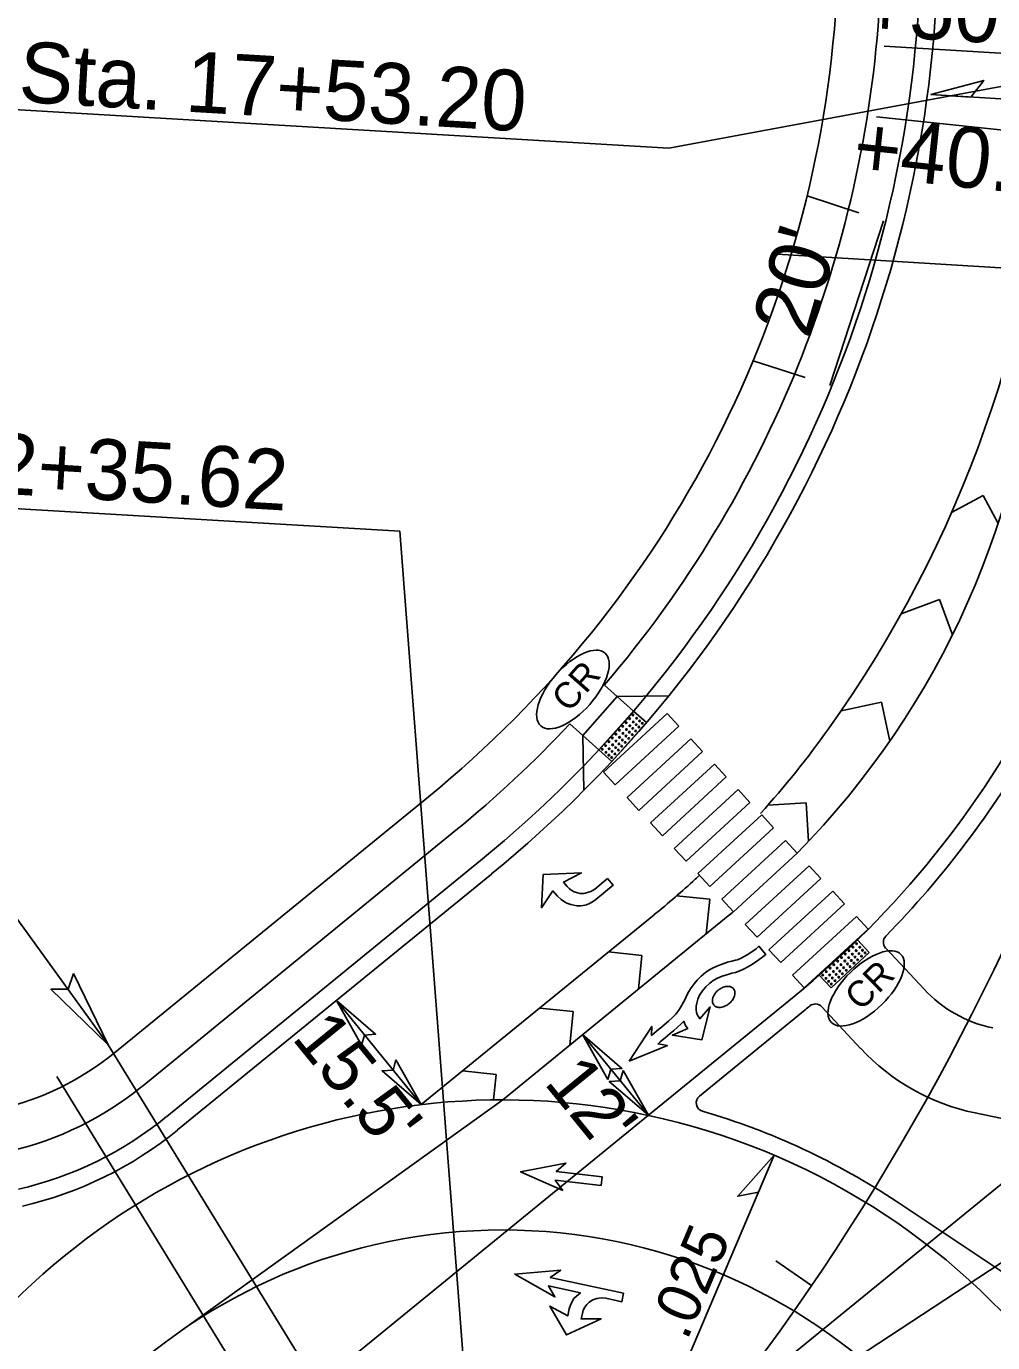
# Model space of a CAD drawing. Extents: x 2010838 to 2015151, y 441905 to 447792.
# Drawn here: x 2011912.5 to 2012023.9, y 445039.2 to 445190.9 of the extents above; entities that cross this region are included whole.
import ezdxf

# ---------------------------------------------------------------- set-up
doc = ezdxf.new("R2010")
doc.units = 0
for name, color, linetype in [('A-Wall-Abov', 7, 'Continuous'), ('A-Wall-Blow', 7, 'Continuous'), ('A-Wall-Comp', 7, 'Continuous'), ('B-Sheet Number', 7, 'Continuous'), ('C-Alignment Geometry', 7, 'Continuous'), ('C-Building', 7, 'Continuous'), ('C-CURB STOPS', 7, 'Continuous'), ('C-Grave Plots', 7, 'Continuous'), ('C-SHBD-TEXT', 7, 'Continuous'), ('C-Surface', 7, 'Continuous'), ('CLRD', 7, 'Continuous'), ('Default_10ft_LIDAR_Contou', 7, 'Continuous'), ('HATCH', 7, 'Continuous'), ('s-Existing Major', 7, 'Continuous'), ('S-Existing Minor', 7, 'Continuous'), ('S-overhead electric', 7, 'Continuous'), ('TEXT-LG', 7, 'Continuous'), ('TEXT-MED', 7, 'Continuous'), ('X2', 7, 'Continuous'), ('X3', 7, 'Continuous'), ('X4', 7, 'Continuous')]:
    doc.layers.add(name, color=color, linetype=linetype)

msp = doc.modelspace()

# ---------------------------------------------------------------- linework, layer by layer
at = {"layer": 'A-Wall-Abov'}
for points in [[(2011979.54, 445092.68), (2011980.18, 445091.91), (2011978.18, 445090.26), (2011977.8, 445089.98), (2011977.48, 445089.8), (2011977.1, 445089.64), (2011976.73, 445089.57), (2011976.43, 445089.54), (2011975.99, 445089.55), (2011975.66, 445089.6), (2011975.29, 445089.68), (2011974.86, 445089.84), (2011974.56, 445090), (2011974.19, 445090.25), (2011973.76, 445090.64), (2011973.25, 445091.26), (2011971.94, 445089.32), (2011972.13, 445093.15), (2011976.52, 445093.32), (2011974.47, 445092.27), (2011974.89, 445091.76), (2011975.15, 445091.48), (2011975.44, 445091.28), (2011975.71, 445091.15), (2011976.09, 445091.02), (2011976.38, 445090.95), (2011976.81, 445090.96), (2011977.22, 445091.05), (2011977.6, 445091.18), (2011978.06, 445091.46)], [(2011979.54, 445092.68), (2011980.18, 445091.91), (2011978.18, 445090.26), (2011977.8, 445089.98), (2011977.48, 445089.8), (2011977.1, 445089.64), (2011976.73, 445089.57), (2011976.43, 445089.54), (2011975.99, 445089.55), (2011975.66, 445089.6), (2011975.29, 445089.68), (2011974.86, 445089.84), (2011974.56, 445090), (2011974.19, 445090.25), (2011973.76, 445090.64), (2011973.25, 445091.26), (2011971.94, 445089.32), (2011972.13, 445093.15), (2011976.52, 445093.32), (2011974.47, 445092.27), (2011974.89, 445091.76), (2011975.15, 445091.48), (2011975.44, 445091.28), (2011975.71, 445091.15), (2011976.09, 445091.02), (2011976.38, 445090.95), (2011976.81, 445090.96), (2011977.22, 445091.05), (2011977.6, 445091.18), (2011978.06, 445091.46)], [(2011982.02, 445071.61), (2011984.63, 445075.63), (2011984.61, 445074.6), (2011985.2, 445075.09), (2011985.79, 445075.58), (2011986.57, 445076.25), (2011987.03, 445076.66), (2011987.41, 445077.06), (2011987.75, 445077.49), (2011987.97, 445077.82), (2011988.3, 445078.41), (2011988.38, 445078.53), (2011988.85, 445079.53), (2011989.18, 445080.07), (2011989.52, 445080.55), (2011989.86, 445080.95), (2011990.32, 445081.42), (2011990.87, 445081.87), (2011991.3, 445082.15), (2011991.58, 445082.31), (2011992.16, 445082.58), (2011992.76, 445082.82), (2011993.38, 445083.03), (2011993.86, 445083.16), (2011994.28, 445083.26), (2011994.54, 445083.32), (2011994.96, 445083.51), (2011995.63, 445083.87), (2011996.19, 445084.23), (2011996.66, 445084.59), (2011997, 445084.88), (2011997.78, 445083.94), (2011997.29, 445083.55), (2011996.76, 445083.16), (2011996.24, 445082.79), (2011995.81, 445082.52), (2011995.23, 445082.22), (2011994.79, 445082.03), (2011994.3, 445081.85), (2011993.86, 445081.75), (2011993.4, 445081.63), (2011992.74, 445081.41), (2011992.21, 445081.18), (2011991.73, 445080.93), (2011991.32, 445080.62), (2011990.86, 445080.2), (2011990.48, 445079.74), (2011990.16, 445079.24), (2011989.96, 445078.76), (2011989.82, 445078.31), (2011989.76, 445077.95), (2011989.76, 445077.53), (2011989.81, 445077.25), (2011989.89, 445077.02), (2011990.05, 445076.7), (2011990.17, 445076.52), (2011991.39, 445077.87), (2011990.43, 445074.1), (2011987.03, 445074.61), (2011988.78, 445075.39), (2011988.62, 445075.61), (2011988.5, 445075.81), (2011988.4, 445076.02), (2011988.32, 445076.23), (2011988.06, 445075.96), (2011987.58, 445075.49), (2011987.19, 445075.15), (2011986.77, 445074.8), (2011986.21, 445074.34), (2011985.61, 445073.84), (2011985.36, 445073.62), (2011986.45, 445073.43)], [(2011974.37, 445056.73), (2011973.51, 445057.92), (2011978.8, 445057.3), (2011978.91, 445058.3), (2011973.62, 445058.91), (2011974.74, 445059.87), (2011969.51, 445058.88)], [(2011981.4, 445044.86), (2011972.93, 445046.7), (2011974.14, 445047.54), (2011968.84, 445047.08), (2011973.47, 445044.45), (2011972.72, 445045.72), (2011976.41, 445044.92), (2011975.95, 445044.55), (2011975.67, 445044.25), (2011975.42, 445043.84), (2011975.27, 445043.5), (2011975.1, 445043.06), (2011974.95, 445042.25), (2011972.89, 445043.38), (2011974.82, 445040.06), (2011978.8, 445041.92), (2011976.5, 445041.91), (2011976.65, 445042.55), (2011976.75, 445042.92), (2011976.92, 445043.27), (2011977.16, 445043.56), (2011977.42, 445043.85), (2011977.84, 445044.11), (2011978.32, 445044.26), (2011978.8, 445044.32), (2011979.34, 445044.29), (2011981.19, 445043.88)]]:
    msp.add_lwpolyline(points, close=True, dxfattribs=at)
for centre, radius, start, end in [((2011993.64, 445078.19), 2.1, 131.7428, 144.4419), ((2011993.56, 445078.28), 1.98, 129.7042, 131.7428), ((2011993.56, 445078.28), 1.98, 127.6657, 129.7042), ((2011993.64, 445078.18), 2.1, 114.9665, 127.6657), ((2011993.6, 445078.27), 2.01, 106.9816, 114.9665), ((2011993.42, 445078.85), 1.4, 84.2522, 106.9816), ((2011993.48, 445079.47), 0.777, 64.0512, 84.2522), ((2011993.49, 445079.5), 0.742, 40.9376, 64.0512), ((2011993.59, 445079.59), 0.613, 39.7042, 40.9376), ((2011993.59, 445079.59), 0.613, 38.4708, 39.7042), ((2011993.49, 445079.51), 0.742, 15.3572, 38.4708), ((2011993.46, 445079.5), 0.777, 355.1563, 15.3572), ((2011993.02, 445078.53), 1.4, 152.4268, 175.1563), ((2011992.4, 445078.58), 0.777, 175.1563, 195.3572), ((2011992.37, 445078.57), 0.742, 195.3572, 218.4708), ((2011993.57, 445078.24), 2.01, 144.4419, 152.4268), ((2011992.27, 445078.49), 0.613, 218.4708, 219.7042), ((2011992.27, 445078.49), 0.613, 219.7042, 220.9376), ((2011992.37, 445078.57), 0.742, 220.9376, 244.0512), ((2011992.27, 445079.81), 2.01, 286.9816, 294.9665), ((2011992.23, 445079.89), 2.1, 294.9665, 307.6657), ((2011992.3, 445079.8), 1.98, 307.6657, 309.7042), ((2011992.3, 445079.8), 1.98, 309.7042, 311.7428), ((2011992.22, 445079.89), 2.1, 311.7428, 324.4419), ((2011992.3, 445079.83), 2.01, 324.4419, 332.4268), ((2011992.84, 445079.55), 1.4, 332.4268, 355.1563), ((2011992.38, 445078.61), 0.777, 244.0512, 264.2522), ((2011992.44, 445079.22), 1.4, 264.2522, 286.9816)]:
    msp.add_arc(centre, radius, start, end, dxfattribs=at)
at = {"layer": 'A-Wall-Blow'}
for p, q in [((2012016.8, 445183.05), (2012051.3, 445180.97)), ((2011987.02, 445033.18), (2011998.75, 445060.79))]:
    msp.add_line(p, q, dxfattribs=at)
at = {"layer": 'A-Wall-Comp'}
for points in [[(2012016.8, 445183.05), (2012022.91, 445184.69), (2012021.41, 445182.77)], [(2011998.75, 445060.79), (2011994.56, 445056.05), (2011996.94, 445056.54)]]:
    msp.add_lwpolyline(points, close=True, dxfattribs=at)
at = {"layer": 'B-Sheet Number'}
for p, q in [((2012008.52, 445169.44), (2012002.55, 445171.4)), ((2012002.31, 445150.43), (2011996.33, 445152.38))]:
    msp.add_line(p, q, dxfattribs=at)
at = {"layer": 'C-Alignment Geometry'}
for p, q in [((2012022.86, 445136.82), (2012019.19, 445134.86)), ((2012024.58, 445133.61), (2012022.86, 445136.82)), ((2012017.81, 445124.84), (2012013.4, 445123.19)), ((2012019.32, 445120.78), (2012017.81, 445124.84)), ((2012011.11, 445113.01), (2012006.46, 445112)), ((2012012.08, 445108.51), (2012011.11, 445113.01)), ((2012002.45, 445101.4), (2011998.03, 445101.14)), ((2012002.71, 445096.98), (2012002.45, 445101.4)), ((2011991.33, 445090.29), (2011987.5, 445090.68)), ((2011990.92, 445086.31), (2011991.33, 445090.29)), ((2011958.07, 445066.61), (2011984.92, 445088.51)), ((2011967.45, 445067.16), (2011993.46, 445088.38)), ((2011983.51, 445083.81), (2011979.64, 445084.21)), ((2011983.12, 445079.94), (2011983.51, 445083.81)), ((2011975.59, 445077.35), (2011971.72, 445077.75)), ((2011975.2, 445073.48), (2011975.59, 445077.35)), ((2011966.69, 445070.09), (2011962.83, 445070.49)), ((2011966.4, 445067.16), (2011966.69, 445070.09))]:
    msp.add_line(p, q, dxfattribs=at)
for centre, radius, start, end in [((2011891.07, 445191.27), 140, 324.4895, 356.5533), ((2011931.52, 445164.32), 98, 315.4891, 356.5533), ((2011915.08, 445174.14), 110.5, 317.9831, 324.4895), ((2011915.08, 445174.14), 110.5, 309.2044, 312.4484), ((2011915.08, 445174.14), 110.5, 312.4484, 312.7901), ((2011931.52, 445164.32), 98, 309.2044, 309.64)]:
    msp.add_arc(centre, radius, start, end, dxfattribs=at)
at = {"layer": 'C-Building'}
msp.add_line((2012003.07, 445045.77), (2011998.94, 445048.59), dxfattribs=at)
at = {"layer": 'C-CURB STOPS'}
for p, q in [((2012011.61, 445084.66), (2012016.03, 445079.92)), ((2012002.31, 445077.53), (2011990.14, 445067.6)), ((2012008.71, 445073.1), (2012004.24, 445077.9)), ((2012033.44, 445063.27), (2012021.92, 445065.66)), ((2012033.44, 445063.27), (2012021.92, 445065.66)), ((2012012.92, 445055.41), (2012026.09, 445046.64))]:
    msp.add_line(p, q, dxfattribs=at)
for centre, radius, start, end in [((2011931.52, 445164.32), 112, 315.6623, 330.169), ((2012012.34, 445085.35), 1, 135.6623, 222.9536), ((2012027.01, 445090.14), 15, 222.9536, 258.2618), ((2011931.52, 445164.32), 112, 309.2044, 309.5749), ((2012003.51, 445077.22), 1, 42.9536, 129.5749), ((2012027.01, 445090.14), 25, 222.9536, 258.2618), ((2012027.01, 445090.14), 25, 222.9536, 258.2618), ((2011990.77, 445066.82), 1, 129.2044, 253.6946), ((2011967.46, 444987.16), 82, 56.3341, 73.6946)]:
    msp.add_arc(centre, radius, start, end, dxfattribs=at)
at = {"layer": 'C-SHBD-TEXT'}
msp.add_line((2012007.71, 445052.8), (2012007.71, 445052.8), dxfattribs=at)
at = {"layer": 'C-Surface'}
for p, q in [((2011967.45, 445067.16), (2011929.56, 445039.97)), ((2011984.25, 445065.38), (2011935.86, 445025.91))]:
    msp.add_line(p, q, dxfattribs=at)
at = {"layer": 'CLRD'}
msp.add_arc((2011767.49, 445206.16), 285, 319.8445, 356.5533, dxfattribs=at)
at = {"layer": 'Default_10ft_LIDAR_Contou'}
for p, q in [((2012051.97, 445189.02), (2011986.6, 445176.88)), ((2011882.62, 445183.01), (2011986.6, 445176.88)), ((2012172.29, 445177.43), (2011992.07, 445030.69)), ((2011824.89, 445140.41), (2011955.59, 445132.71)), ((2011985.31, 445022.37), (2012164.65, 445140.22)), ((2011962.94, 445036.96), (2011955.59, 445132.71))]:
    msp.add_line(p, q, dxfattribs=at)
at = {"layer": 'HATCH'}
for p, q in [((2011986.42, 445111.71), (2011979.06, 445104.94)), ((2011987.77, 445110.24), (2011986.42, 445111.71)), ((2011980.41, 445103.47), (2011987.77, 445110.24)), ((2011989.15, 445108.79), (2011981.79, 445102.02)), ((2011990.5, 445107.31), (2011989.15, 445108.79)), ((2011983.14, 445100.54), (2011990.5, 445107.31)), ((2011991.87, 445105.86), (2011984.51, 445099.09)), ((2011993.23, 445104.39), (2011991.87, 445105.86)), ((2011979.06, 445104.94), (2011980.41, 445103.47)), ((2011985.87, 445097.62), (2011993.23, 445104.39)), ((2011994.6, 445102.93), (2011987.24, 445096.16)), ((2011995.96, 445101.46), (2011994.6, 445102.93)), ((2011981.79, 445102.02), (2011983.14, 445100.54)), ((2011988.6, 445094.69), (2011995.96, 445101.46)), ((2011997.33, 445100.01), (2011989.97, 445093.24)), ((2011998.68, 445098.54), (2011997.33, 445100.01)), ((2011984.51, 445099.09), (2011985.87, 445097.62)), ((2011991.32, 445091.77), (2011998.68, 445098.54)), ((2012000.06, 445097.08), (2011992.7, 445090.31)), ((2012001.41, 445095.61), (2012000.06, 445097.08)), ((2011987.24, 445096.16), (2011988.6, 445094.69)), ((2011994.05, 445088.84), (2012001.41, 445095.61)), ((2011989.97, 445093.24), (2011991.32, 445091.77)), ((2012002.78, 445094.16), (2011995.42, 445087.39)), ((2012004.14, 445092.68), (2012002.78, 445094.16)), ((2011996.78, 445085.91), (2012004.14, 445092.68)), ((2011992.7, 445090.31), (2011994.05, 445088.84)), ((2012005.51, 445091.23), (2011998.15, 445084.46)), ((2012006.86, 445089.76), (2012005.51, 445091.23)), ((2011999.51, 445082.99), (2012006.86, 445089.76)), ((2011958.07, 445066.61), (2011984.92, 445088.51)), ((2011995.42, 445087.39), (2011996.78, 445085.91)), ((2012008.24, 445088.3), (2012000.88, 445081.53)), ((2012009.59, 445086.83), (2012008.24, 445088.3)), ((2012002.23, 445080.06), (2012009.59, 445086.83)), ((2011998.15, 445084.46), (2011999.51, 445082.99)), ((2012000.88, 445081.53), (2012002.23, 445080.06)), ((2011958.07, 445066.61), (2011948.28, 445078.62)), ((2011984.25, 445065.38), (2011976.67, 445074.68))]:
    msp.add_line(p, q, dxfattribs=at)
msp.add_circle((2011967.46, 444987.16), 65, dxfattribs=at)
for centre, radius, start, end in [((2011891.07, 445191.27), 140, 324.4895, 356.5533), ((2011967.46, 444987.16), 80, 77.8866, 152.8308)]:
    msp.add_arc(centre, radius, start, end, dxfattribs=at)
at = {"layer": 's-Existing Major'}
for points in [[(2011917.95, 445081.72), (2011921.98, 445073.52), (2011915.37, 445079.91), (2011917.34, 445079.92)], [(2011951.19, 445073.45), (2011948.28, 445078.62), (2011952.8, 445074.72), (2011951.52, 445074.64)], [(2011979.58, 445069.51), (2011976.67, 445074.68), (2011981.19, 445070.78), (2011979.91, 445070.7)], [(2011955.15, 445071.78), (2011958.07, 445066.61), (2011953.55, 445070.51), (2011954.83, 445070.59)], [(2011981.34, 445070.55), (2011984.25, 445065.38), (2011979.73, 445069.28), (2011981.01, 445069.36)]]:
    msp.add_lwpolyline(points, close=True, dxfattribs=at)
at = {"layer": 'S-Existing Minor'}
for p, q in [((2011765.91, 445288.76), (2011921.98, 445073.52)), ((2012042.64, 445186.76), (2012011.45, 445188.64)), ((2012041.98, 445177.19), (2012010.57, 445180.5)), ((2011948.28, 445078.62), (2011958.07, 445066.61)), ((2011976.67, 445074.68), (2011984.25, 445065.38))]:
    msp.add_line(p, q, dxfattribs=at)
at = {"layer": 'S-overhead electric'}
for p, q in [((2011929.97, 445063.69), (2011966.16, 445093.2)), ((2011984.25, 445065.38), (2012001.05, 445079.08))]:
    msp.add_line(p, q, dxfattribs=at)
for centre, radius, start, end in [((2011877.67, 445201.69), 140, 309.2044, 356.5533), ((2011931.52, 445164.32), 110, 309.2044, 356.5533), ((2011967.46, 444987.16), 80, 37.7074, 77.8866), ((2011902.16, 445097.78), 44, 283.0186, 309.2044)]:
    msp.add_arc(centre, radius, start, end, dxfattribs=at)
at = {"layer": 'TEXT-LG'}
for p, q in [((2011982.54, 445111.99), (2011979.18, 445114.99)), ((2011976.68, 445109.18), (2011980.67, 445113.65)), ((2011986.61, 445113.76), (2011980.67, 445113.65)), ((2011982.54, 445111.99), (2011978.54, 445107.51)), ((2011982.54, 445111.99), (2011984.03, 445110.66)), ((2011978.54, 445107.51), (2011975.19, 445110.52)), ((2011984.03, 445110.66), (2011980.03, 445106.18)), ((2011976.79, 445102.82), (2011976.68, 445109.18)), ((2011980.03, 445106.18), (2011978.54, 445107.51)), ((2011922.7, 445072.6), (2011958.89, 445102.11)), ((2011925.87, 445068.72), (2011962.05, 445098.24)), ((2012008.36, 445085.61), (2012003.95, 445081.54)), ((2012008.36, 445085.61), (2012009.72, 445084.14)), ((2012009.72, 445084.14), (2012005.31, 445080.07)), ((2012005.31, 445080.07), (2012003.95, 445081.54))]:
    msp.add_line(p, q, dxfattribs=at)
for centre in [(2011982.47, 445111.53), (2011980.9, 445109.78), (2011981.3, 445110.23), (2011981.69, 445110.65), (2011981.72, 445109.86), (2011982.09, 445111.1), (2011982.11, 445110.29), (2011982.45, 445109.98), (2011982.51, 445110.74), (2011982.85, 445110.43), (2011982.89, 445111.16), (2011983.17, 445110.15), (2011983.23, 445110.85), (2011983.56, 445110.57), (2011979.71, 445108.45), (2011980.1, 445108.88), (2011980.5, 445109.32), (2011980.52, 445108.52), (2011980.92, 445108.96), (2011981.26, 445108.65), (2011981.32, 445109.42), (2011981.58, 445108.37), (2011981.66, 445109.11), (2011981.99, 445108.83), (2011982.06, 445109.55), (2011982.39, 445109.27), (2011982.77, 445109.7), (2011978.93, 445107.58), (2011979.31, 445108.01), (2011979.35, 445107.22), (2011979.69, 445106.9), (2011979.73, 445107.64), (2011980.07, 445107.33), (2011980.13, 445108.09), (2011980.4, 445107.05), (2011980.47, 445107.78), (2011980.8, 445107.5), (2011980.86, 445108.2), (2011981.18, 445107.93), (2011980.01, 445106.63), (2012006.96, 445083.97), (2012007.39, 445084.36), (2012007.83, 445084.77), (2012008.21, 445084.37), (2012008.25, 445085.16), (2012008.52, 445084.03), (2012008.63, 445084.76), (2012008.94, 445084.41), (2012009.24, 445084.11), (2012005.63, 445082.75), (2012006.08, 445083.15), (2012006.46, 445082.75), (2012006.52, 445083.57), (2012006.9, 445083.17), (2012007.21, 445082.83), (2012007.35, 445083.57), (2012007.51, 445082.52), (2012007.65, 445083.23), (2012007.77, 445083.96), (2012007.95, 445082.92), (2012008.08, 445083.62), (2012008.37, 445083.31), (2012008.82, 445083.72), (2012004.35, 445081.56), (2012004.73, 445081.16), (2012004.77, 445081.95), (2012005.15, 445081.55), (2012005.21, 445082.36), (2012005.46, 445081.21), (2012005.59, 445081.96), (2012005.9, 445081.62), (2012006.02, 445082.35), (2012006.2, 445081.31), (2012006.32, 445082), (2012006.62, 445081.7), (2012006.77, 445082.41), (2012007.07, 445082.1), (2012005.04, 445080.82), (2012005.34, 445080.51), (2012005.76, 445080.9)]:
    msp.add_circle(centre, 0.0869, dxfattribs=at)
for centre, radius, start, end in [((2011877.67, 445201.69), 128.5, 309.2044, 356.5533), ((2011877.67, 445201.69), 133.5, 319.5013, 356.5533), ((2011877.67, 445201.69), 133.5, 309.2044, 316.9297), ((2011902.16, 445097.78), 32.5, 283.0186, 309.2044), ((2011902.16, 445097.78), 37.5, 283.0186, 309.2044)]:
    msp.add_arc(centre, radius, start, end, dxfattribs=at)
at = {"layer": 'TEXT-MED'}
msp.add_line((2011928.71, 445065.24), (2011964.9, 445094.75), dxfattribs=at)
for centre, radius, start, end in [((2011877.67, 445201.69), 138, 309.2044, 356.5533), ((2011902.16, 445097.78), 42, 283.0186, 309.2044)]:
    msp.add_arc(centre, radius, start, end, dxfattribs=at)
at = {"layer": 'X2'}
msp.add_line((2012005.16, 445149.5), (2012011.37, 445168.51), dxfattribs=at)
at = {"layer": 'X3'}
for p, q in [((2011999.11, 445164.65), (2012088.07, 445159.29)), ((2011921.98, 445073.52), (2011962.71, 445007.14)), ((2011916.03, 445069.87), (2011956.76, 445003.49))]:
    msp.add_line(p, q, dxfattribs=at)
at = {"layer": 'X4'}
for centre, major_axis in [((2011975.55, 445114.47), (3.71, 4.2)), ((2012009.36, 445080.01), (4.01, 3.92))]:
    msp.add_ellipse(centre, major_axis=major_axis, ratio=0.462467, dxfattribs=at)

# ---------------------------------------------------------------- texts
at = {"layer": 'A-Wall-Blow'}
msp.add_text('.025', height=5, rotation=66.9797, dxfattribs=at).set_placement((2011988.7, 445039.32))
at = {"layer": 'C-Grave Plots'}
for s, height, rotation, p in [("20'", 7, 73.5449, (2012002.8, 445154.73)), ("15.5'", 6, 309.2044, (2011943.04, 445074.26)), ("12'", 6, 309.2044, (2011972.11, 445069.1))]:
    msp.add_text(s, height=height, rotation=rotation, dxfattribs=at).set_placement(p)
at = {"layer": 'Default_10ft_LIDAR_Contou'}
for s, p in [('-Y- PT Sta. 17+53.20', (2011881.95, 445183.98)), ('-RND1- PCC Sta.  12+35.62', (2011824.86, 445142.03))]:
    msp.add_text(s, height=7, rotation=356.6264, dxfattribs=at).set_placement(p)
at = {"layer": 'S-Existing Minor'}
for s, rotation, p in [('+50.38', 356.5533, (2012008.73, 445189.91)), ('+40.38', 353.9754, (2012007.64, 445173.74))]:
    msp.add_text(s, height=7, rotation=rotation, dxfattribs=at).set_placement(p)
at = {"layer": 'X4'}
for rotation, p in [(48.5593, (2011975.1, 445111.72)), (44.3512, (2012008.71, 445077.31))]:
    msp.add_text('CR', height=3, rotation=rotation, dxfattribs=at).set_placement(p)

doc.saveas('drawing.dxf')
